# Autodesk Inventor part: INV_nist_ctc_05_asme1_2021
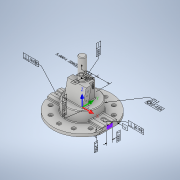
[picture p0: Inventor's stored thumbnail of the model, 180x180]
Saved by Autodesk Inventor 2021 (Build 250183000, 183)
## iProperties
Created: 2016-11
Part Number: INV_nist_ctc_05_asme1_2021
Material: Generic
Document SubType Name: Modeling
Designer: t_liuje
Density: 1 g/cm^3
Appearance: Default
Author: t_liuje
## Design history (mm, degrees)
node "Blocks"
  sketch "Block1"
    geometry: L1 (-127.723, 75.933)-(-118.256, 65.644); L2 (-128.66, 64.324)-(-128.66, 75.568); L3 (-131.763, 64.324)-(-128.66, 64.324); L4 (-131.763, 76.486)-(-131.763, 64.324); L5 (-115.842, 67.6)-(-126.107, 78.7); L6 (-115.125, 79.324)-(-115.125, 67.916); L7 (-111.993, 79.324)-(-115.125, 79.324); L8 (-111.993, 67.841)-(-111.993, 79.324); L9 (-109.981, 79.324)-(-109.981, 68.52); L10 (-106.849, 79.324)-(-109.981, 79.324); L11 (-106.849, 68.52)-(-106.849, 79.324); L12 (-91.045, 67.427)-(-105.757, 67.427); L13 (-100.154, 70.244)-(-91.103, 70.244); L14 (-74.895, 79.324)-(-100.498, 79.324); L15 (-74.895, 76.163)-(-74.895, 79.324); L16 (-81.304, 76.163)-(-74.895, 76.163); L17 (-81.304, 64.324)-(-81.304, 76.163); L18 (-84.407, 64.324)-(-81.304, 64.324); L19 (-84.407, 76.163)-(-84.407, 64.324); L20 (-100.097, 76.163)-(-84.407, 76.163); L21 (-90.585, 73.347)-(-100.212, 73.347); L22 (-105.786, 64.324)-(-90.585, 64.324); A1 r 3.517 centre (-115.51, 67.841) between (-118.256, 65.644) and (-111.993, 67.841); A2 r 0.54 centre (-128.12, 75.568) between (-127.723, 75.933) and (-128.66, 75.568); A3 r 3.261 centre (-128.502, 76.486) between (-126.107, 78.7) and (-131.763, 76.486); A4 r 0.415 centre (-115.538, 67.881) between (-115.842, 67.6) and (-115.125, 67.916); A5 r 4.196 centre (-105.786, 68.52) between (-109.981, 68.52) and (-105.786, 64.324); A6 r 1.093 centre (-105.757, 68.52) between (-106.849, 68.52) and (-105.757, 67.427); A7 r 1.417 centre (-91.225, 68.832) between (-91.045, 67.427) and (-91.103, 70.244); A8 r 4.547 centre (-100.498, 74.777) between (-100.498, 79.324) and (-100.154, 70.244); A9 r 1.41 centre (-100.212, 74.757) between (-100.097, 76.163) and (-100.212, 73.347); A10 r 4.568 centre (-91.304, 68.836) between (-90.585, 64.324) and (-90.585, 73.347); 1 further point
    constraints: 44 end point, 20 point on circle, 10 centre point, 1 coincident
  sketch "Block2"
    geometry: L1 (43.362, -16.74)-(33.073, -26.207); L2 (31.753, -15.802)-(42.997, -15.802); L3 (31.753, -12.7)-(31.753, -15.802); L4 (43.915, -12.7)-(31.753, -12.7); L5 (35.029, -28.62)-(46.129, -18.355); L6 (46.753, -29.338)-(35.345, -29.338); L7 (46.753, -32.47)-(46.753, -29.338); L8 (35.27, -32.47)-(46.753, -32.47); L9 (46.753, -34.481)-(35.949, -34.481); L10 (46.753, -37.613)-(46.753, -34.481); L11 (35.949, -37.613)-(46.753, -37.613); L12 (34.856, -53.417)-(34.856, -38.706); L13 (37.673, -44.308)-(37.673, -53.36); L14 (46.753, -69.567)-(46.753, -43.964); L15 (43.592, -69.567)-(46.753, -69.567); L16 (43.592, -63.158)-(43.592, -69.567); L17 (31.753, -63.158)-(43.592, -63.158); L18 (31.753, -60.056)-(31.753, -63.158); L19 (43.592, -60.056)-(31.753, -60.056); L20 (43.592, -44.366)-(43.592, -60.056); L21 (40.776, -53.877)-(40.776, -44.251); L22 (31.753, -38.677)-(31.753, -53.877); A1 r 3.517 centre (35.27, -28.953) between (33.073, -26.207) and (35.27, -32.47); A2 r 0.54 centre (42.997, -16.342) between (43.362, -16.74) and (42.997, -15.802); A3 r 3.261 centre (43.915, -15.961) between (46.129, -18.355) and (43.915, -12.7); A4 r 0.415 centre (35.31, -28.924) between (35.029, -28.62) and (35.345, -29.338); A5 r 4.196 centre (35.949, -38.677) between (35.949, -34.481) and (31.753, -38.677); A6 r 1.093 centre (35.949, -38.706) between (35.949, -37.613) and (34.856, -38.706); A7 r 1.417 centre (36.262, -53.237) between (34.856, -53.417) and (37.673, -53.36); A8 r 4.547 centre (42.207, -43.964) between (46.753, -43.964) and (37.673, -44.308); A9 r 1.41 centre (42.187, -44.251) between (43.592, -44.366) and (40.776, -44.251); A10 r 4.568 centre (36.265, -53.159) between (31.753, -53.877) and (40.776, -53.877); 1 further point
    constraints: 44 end point, 20 point on circle, 10 centre point
sketch "Sketch1"
  geometry: L1 (263.525, -92.838)-(263.525, 92.838); L2 (-263.525, -92.838)-(-263.525, 92.838); A1 r 279.4 centre (0, 0) between (-263.525, -92.838) and (263.525, -92.838); A2 r 279.4 centre (0, 0) between (263.525, 92.838) and (-263.525, 92.838); 1 further point
  constraints: 4 end point, 4 point on circle, 2 centre point, 2 vertical, 1 coincident, 1 parallel
  dimensions: "d1" = 527.05 distance between parallel lines of L2 L1; "d2" = 279.4 radius of A1; "d3" = 279.4 radius of A2
extrude "Extrusion1" new body sketch "Sketch1" distance "d4" = 25.4; taper "d5" = 0 deg
sketch "Sketch2"
  geometry: L1 (22.988, 25.4)-(22.988, 44.767); L2 (162.688, 25.4)-(162.688, 44.767); L3 (22.988, 25.4)-(162.688, 25.4); L4 (0, 25.4)-(185.676, 25.4) reference; L5 (48.871, 52.336)-(136.806, 52.336); L6 (92.838, 0)-(92.838, 107.422); A1 r 203.2 centre (92.838, -146.05) between (162.688, 44.767) and (136.806, 52.336); A2 r 203.2 centre (92.838, -146.05) between (48.871, 52.336) and (22.988, 44.767)
  constraints: 10 end point, 4 point on circle, 3 vertical, 2 centre point, 1 collinear, 1 horizontal, 1 parallel, 1 other
  dimensions: "d6" = 139.7 distance of L1.start L2.start; "d8" = 171.45 distance from line of L3 A1.centre; "d9" = 87.9348 distance of L5.start L5.end; "d10" = 203.2 radius of A2; "d11" = 203.2 radius of A1
extrude "Extrusion2" join sketch "Sketch2" stored distance "d12" = 25.4; taper "d13" = 0 deg
sketch "Sketch3"
  geometry: C1 r 152.4 at (0, 0); 1 further point
  constraints: 1 centre point, 1 coincident
  dimensions: "d14" = 304.8 diameter of C1
extrude "Extrusion3" join sketch "Sketch3" distance "d15" = 101.6; taper "d16" = 0 deg
sketch "Sketch4"
  geometry: L1 (0, 0)-(321.097, 0); L2 (279.4, 50.8)-(279.4, 0); L3 (279.4, 50.8)-(127, 84.586); L4 (127, -152.4)-(127, 152.4) reference; L5 (279.4, 0)-(127, 33.786); L6 (127, 33.786)-(127, 84.586)
  constraints: 10 end point, 2 point on line, 2 vertical, 1 horizontal, 1 parallel
  dimensions: "d17" = 50.8 distance of L2.start L2.end; "d18" = 77.5 deg angle of L4 L3; "d19" = 152.4 distance between parallel lines of L4 L2
extrude "Extrusion4" join sketch "Sketch4" stored distance "d21" = 177.8; taper "d22" = 0 deg
sketch "Sketch5"
  geometry: L1 (-88.9, -50.8)-(88.9, -50.8) reference; L2 (0, -128.984)-(0, 120.055); L3 (-63.5, -50.8)-(-63.5, 59.185); L4 (63.5, -50.8)-(63.5, 59.185); L5 (63.5, -50.8)-(-63.5, -50.8); A1 r 127 centre (0, -50.8) between (63.5, 59.185) and (-63.5, 59.185); 1 further point
  constraints: 8 end point, 3 vertical, 2 point on circle, 2 point on line, 1 centre point, 1 collinear, 1 midpoint, 1 other
  dimensions: "d23" = 127 distance between parallel lines of L4 L3; "d24" = 127 radius of A1
extrude "Extrusion5" join sketch "Sketch5" stored distance "d25" = 177.8; taper "d26" = 0 deg
sketch "Sketch6"
  geometry: C1 r 31.75 at (88.9, 50.8); 1 further point
  constraints: 1 centre point, 1 coincident
  dimensions: "d27" = 63.5 diameter of C1
extrude "Extrusion6" join sketch "Sketch6" distance "d28" = 203.2; taper "d29" = 0 deg
sketch "Sketch7"
  geometry: L1 (0, 63.017)-(60.325, 63.017); L2 (60.325, 24.917)-(0, 24.917); L3 (0, 24.917)-(0, 63.017); L4 (263.525, 43.967)-(-126.76, 43.967); L5 (0, 87.935)-(0, 0) reference; A1 r 19.05 centre (60.325, 43.967) between (60.325, 24.917) and (60.325, 63.017)
  constraints: 8 end point, 2 horizontal, 2 point on circle, 2 tangent, 1 centre point, 1 collinear, 1 parallel, 1 other
  dimensions: "d31" = 38.1 distance of L1.end L2.start; "d32" = 60.325 distance from line of L3 A1.centre
extrude "Extrusion7" cut sketch "Sketch7" distance "d33" = 8.89; taper "d34" = 0 deg
hole "Hole1" diameter "d37" = 7.9502; stored, may be unused: countersink angle "d41" = 82 deg, drill point angle "d43" = 118 deg; dims "d35" = 28.575, "d36" = 19.05, "d38" = 19.05, "d39" = 9.525, "d40" = 6.35, "d42" = 30.48
hole "Hole2" diameter "d46" = 7.9502; stored, may be unused: countersink angle "d50" = 82 deg, drill point angle "d52" = 118 deg; dims "d44" = 25.4, "d45" = 25.4, "d47" = 19.05, "d48" = 9.525, "d49" = 6.35, "d51" = 30.48
mirror "Mirror1"
fillet "Fillet1" dims "d53" = 6.35
chamfer "Chamfer1" distance "d54" = 6.35; stored, may be unused: second distance "d55" = 3.175, angle "d56" = 45 deg
hole "Hole3" diameter "d59" = 10.7188; stored, may be unused: countersink angle "d63" = 82 deg, drill point angle "d65" = 118 deg; dims "d57" = 38.1, "d58" = 25.4, "d60" = 19.05, "d61" = 9.525, "d62" = 6.35, "d64" = 30.48
pattern_linear "Rectangular Pattern1" dims "d68" = 35.7632
mirror "Mirror2"
sketch "Sketch8" dims "d69" = 444.5
  geometry: 3 further points
  constraints: 1 coincident, 1 vertical alignment, 2 other
hole "Hole4" sketch "Sketch8" at (0, 222.25) diameter "d70" = 19.05; stored, may be unused: countersink angle "d74" = 82 deg, drill point angle "d76" = 0 deg; dims "d71" = 19.05, "d72" = 38.1, "d73" = 12.7, "d75" = 30.48
pattern_circular "Circular Pattern1" dims angle "d78" = 60 deg
pattern_circular "Circular Pattern2" dims angle "d81" = -60 deg
mirror "Mirror3"
hole "Hole5" diameter "d85" = 254; stored, may be unused: countersink angle "d89" = 82 deg, drill point angle "d91" = 0 deg; dims "d83" = 25.4, "d84" = 25.4, "d86" = 19.05, "d87" = 9.525, "d88" = 6.35, "d90" = 101.6
fillet "Fillet2" dims "d92" = 6.35
sketch "Sketch11"
  geometry: L1 (59.185, -146.05)-(59.185, 0) reference; L2 (59.185, 0)-(0, 0) reference; 1 further point
  dimensions: "d158" = 27.432 dimension on L1; "d159" = 12.7 dimension on L2
extrude "Extrusion9" cut sketch "Sketch11" distance "d184" = 2.54; taper "d185" = 0 deg
workplane "Work Plane1"
sketch "Sketch12"
  geometry: L1 (0, 138.528)-(0, 100.428)
  constraints: 2 end point, 1 vertical
  dimensions: "d207" = 38.1 distance of L1.start L1.end
split "Split1"
split "Split2"
body "Solid1"
node "Annotations"
node "Tolerance Features"
sketch "Sketch9"
  geometry: L1 (118.238, 43.446)-(67.438, 43.446); L2 (67.438, 43.446)-(67.438, 11.696); L3 (118.238, 11.696)-(118.238, 43.446); L4 (111.888, 43.446)-(73.788, 43.446) reference; L5 (118.238, 43.446)-(86.488, 11.696); L6 (111.054, 43.446)-(79.304, 11.696); L7 (118.238, 36.262)-(93.672, 11.696); L8 (118.238, 29.078)-(100.857, 11.696); L9 (118.238, 21.894)-(108.041, 11.696); L10 (118.238, 14.709)-(115.225, 11.696); L11 (103.87, 43.446)-(72.12, 11.696); L12 (96.686, 43.446)-(67.438, 14.199); L13 (89.501, 43.446)-(67.438, 21.383); L14 (82.317, 43.446)-(67.438, 28.567); L15 (75.133, 43.446)-(67.438, 35.751); L16 (67.949, 43.446)-(67.438, 42.936)
  constraints: 30 end point, 16 point on line, 2 horizontal, 1 collinear, 1 parallel, 1 perpendicular, 10 other
sketch "Sketch10"
  geometry: L1 (73.788, 43.446)-(111.888, 43.446) reference; L2 (118.238, 43.446)-(118.238, 11.696); L3 (118.238, 11.696)-(67.438, 11.696); L4 (67.438, 11.696)-(67.438, 43.446); L5 (111.888, 43.446)-(73.788, 43.446) reference; L6 (67.438, 11.696)-(112.339, 11.696); L7 (67.438, 18.88)-(92.004, 43.446); L8 (67.438, 26.065)-(84.82, 43.446); L9 (67.438, 33.249)-(77.636, 43.446); L10 (67.438, 40.433)-(70.451, 43.446); L11 (74.622, 11.696)-(106.372, 43.446); L12 (81.807, 11.696)-(113.557, 43.446); L13 (88.991, 11.696)-(118.238, 40.944); L14 (96.175, 11.696)-(118.238, 33.759); L15 (103.359, 11.696)-(118.238, 26.575); L16 (110.543, 11.696)-(118.238, 19.391); L17 (117.728, 11.696)-(118.238, 12.207); L18 (67.438, 11.696)-(99.188, 43.446)
  constraints: 32 end point, 16 point on line, 3 horizontal, 1 parallel, 1 vertical, 10 other
node "Block2:1" dims "d158" = 27.432, "d159" = 12.7
node "Shaft 1" dims "d117" = 9.20107 (derived), "d118" = 2.19232 (derived), "d124" = 8.97666 (derived), "d125" = 7.08407 (derived), "d126" = 0.127 (derived), "d127" = 0 (derived), "d128" = 0 (derived), "d151" = 8.77194 (derived), "d152" = 1.92396 (derived), "d153" = 2.52724 (derived), "d154" = 6.28333 (derived), "d155" = 0.254 (derived), "d156" = 0 (derived), "d157" = 0 (derived), "d162" = 6.82626 (derived), "d163" = 8.91182 (derived), "d164" = 0.889 (derived), "d165" = 0 (derived), "d166" = 0 (derived), "d167" = 2.24004 (derived), "d168" = 3.53865 (derived), "d169" = 0.254 (derived), "d170" = 0 (derived), "d171" = 0 (derived)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
node "Datum Reference Frame 1"
node "Simple Hole 1" dims "d117" = 9.20107 (derived), "d118" = 2.19232 (derived), "d124" = 8.97666 (derived), "d125" = 7.08407 (derived), "d126" = 0.127 (derived), "d127" = 0 (derived), "d128" = 0 (derived), "d151" = 8.77194 (derived), "d152" = 1.92396 (derived), "d153" = 2.52724 (derived), "d154" = 6.28333 (derived), "d155" = 0.254 (derived), "d156" = 0 (derived), "d157" = 0 (derived), "d162" = 6.82626 (derived), "d163" = 8.91182 (derived), "d164" = 0.889 (derived), "d165" = 0 (derived), "d166" = 0 (derived), "d167" = 2.24004 (derived), "d168" = 3.53865 (derived), "d169" = 0.254 (derived), "d170" = 0 (derived), "d171" = 0 (derived)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
node "Datum Reference Frame 2"
node "Planar Surface 1"
node "Planar Surface 2" dims "d117" = 9.20107 (derived), "d118" = 2.19232 (derived), "d124" = 8.97666 (derived), "d125" = 7.08407 (derived), "d126" = 0.127 (derived), "d127" = 0 (derived), "d128" = 0 (derived), "d151" = 8.77194 (derived), "d152" = 1.92396 (derived), "d153" = 2.52724 (derived), "d154" = 6.28333 (derived), "d155" = 0.254 (derived), "d156" = 0 (derived), "d157" = 0 (derived), "d162" = 6.82626 (derived), "d163" = 8.91182 (derived), "d164" = 0.889 (derived), "d165" = 0 (derived), "d166" = 0 (derived), "d167" = 2.24004 (derived), "d168" = 3.53865 (derived), "d169" = 0.254 (derived), "d170" = 0 (derived), "d171" = 0 (derived)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
node "Datum Identifier 3" dims "d117" = 9.20107 (derived), "d118" = 2.19232 (derived), "d124" = 8.97666 (derived), "d125" = 7.08407 (derived), "d126" = 0.127 (derived), "d127" = 0 (derived), "d128" = 0 (derived), "d151" = 8.77194 (derived), "d152" = 1.92396 (derived), "d153" = 2.52724 (derived), "d154" = 6.28333 (derived), "d155" = 0.254 (derived), "d156" = 0 (derived), "d157" = 0 (derived), "d162" = 6.82626 (derived), "d163" = 8.91182 (derived), "d164" = 0.889 (derived), "d165" = 0 (derived), "d166" = 0 (derived), "d167" = 2.24004 (derived), "d168" = 3.53865 (derived), "d169" = 0.254 (derived), "d170" = 0 (derived), "d171" = 0 (derived)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
node "Datum Reference Frame 3"
node "Cylindrical Surface 3"
node "Feature Control Frame 5"
node "Planar Surface 3"
node "Planar Surface 4" dims "d117" = 9.20107 (derived), "d118" = 2.19232 (derived), "d124" = 8.97666 (derived), "d125" = 7.08407 (derived), "d126" = 0.127 (derived), "d127" = 0 (derived), "d128" = 0 (derived), "d151" = 8.77194 (derived), "d152" = 1.92396 (derived), "d153" = 2.52724 (derived), "d154" = 6.28333 (derived), "d155" = 0.254 (derived), "d156" = 0 (derived), "d157" = 0 (derived), "d162" = 6.82626 (derived), "d163" = 8.91182 (derived), "d164" = 0.889 (derived), "d165" = 0 (derived), "d166" = 0 (derived), "d167" = 2.24004 (derived), "d168" = 3.53865 (derived), "d169" = 0.254 (derived), "d170" = 0 (derived), "d171" = 0 (derived)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
node "Datum Identifier 4" dims "d117" = 9.20107 (derived), "d118" = 2.19232 (derived), "d124" = 8.97666 (derived), "d125" = 7.08407 (derived), "d126" = 0.127 (derived), "d127" = 0 (derived), "d128" = 0 (derived), "d151" = 8.77194 (derived), "d152" = 1.92396 (derived), "d153" = 2.52724 (derived), "d154" = 6.28333 (derived), "d155" = 0.254 (derived), "d156" = 0 (derived), "d157" = 0 (derived), "d162" = 6.82626 (derived), "d163" = 8.91182 (derived), "d164" = 0.889 (derived), "d165" = 0 (derived), "d166" = 0 (derived), "d167" = 2.24004 (derived), "d168" = 3.53865 (derived), "d169" = 0.254 (derived), "d170" = 0 (derived), "d171" = 0 (derived)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
node "Datum Reference Frame 4"
node "Datum Reference Frame 5"
node "Planar Surface 5"
node "Feature Control Frame 7"
node "Datum Reference Frame 6"
node "Feature Control Frame 6"
node "Planar Surface 6"
node "Feature Control Frame 9"
node "Shaft 2"
node "Feature Control Frame 17"
node "Hole Note 1"
node "Feature Control Frame 22"
node "Datum Identifier 8" dims "d117" = 9.20107 (derived), "d118" = 2.19232 (derived), "d124" = 8.97666 (derived), "d125" = 7.08407 (derived), "d126" = 0.127 (derived), "d127" = 0 (derived), "d128" = 0 (derived), "d151" = 8.77194 (derived), "d152" = 1.92396 (derived), "d153" = 2.52724 (derived), "d154" = 6.28333 (derived), "d155" = 0.254 (derived), "d156" = 0 (derived), "d157" = 0 (derived), "d162" = 6.82626 (derived), "d163" = 8.91182 (derived), "d164" = 0.889 (derived), "d165" = 0 (derived), "d166" = 0 (derived), "d167" = 2.24004 (derived), "d168" = 3.53865 (derived), "d169" = 0.254 (derived), "d170" = 0 (derived), "d171" = 0 (derived)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
node "Linear Dimension 8" dims "d375" = 50.8 (derived)
node "Linear Dimension 9" dims "d378" = 31.75 (derived)
node "Linear Dimension 10" dims "d381" = 50.8 (derived)
node "Linear Dimension 11" dims "d384" = 31.75 (derived)
node "Linear Dimension 12" dims "d387" = 127 (derived)
node "Diameter Dimension 2" dims "d391" = 304.8 (derived)
node "Feature Control Frame 23"
node "Diameter Dimension 1" dims "d398" = 63.5 (derived)
node "Feature Control Frame 24"
node "Datum Identifier 9" dims "d117" = 9.20107 (derived), "d118" = 2.19232 (derived), "d124" = 8.97666 (derived), "d125" = 7.08407 (derived), "d126" = 0.127 (derived), "d127" = 0 (derived), "d128" = 0 (derived), "d151" = 8.77194 (derived), "d152" = 1.92396 (derived), "d153" = 2.52724 (derived), "d154" = 6.28333 (derived), "d155" = 0.254 (derived), "d156" = 0 (derived), "d157" = 0 (derived), "d162" = 6.82626 (derived), "d163" = 8.91182 (derived), "d164" = 0.889 (derived), "d165" = 0 (derived), "d166" = 0 (derived), "d167" = 2.24004 (derived), "d168" = 3.53865 (derived), "d169" = 0.254 (derived), "d170" = 0 (derived), "d171" = 0 (derived)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
other parameters: "d0" = 558.8, "d7" = 203.2, "d209" = 0, "d210" = -50.8, "d211" = 0, "d212" = 90 deg, "d213" = 0, "d214" = 0
